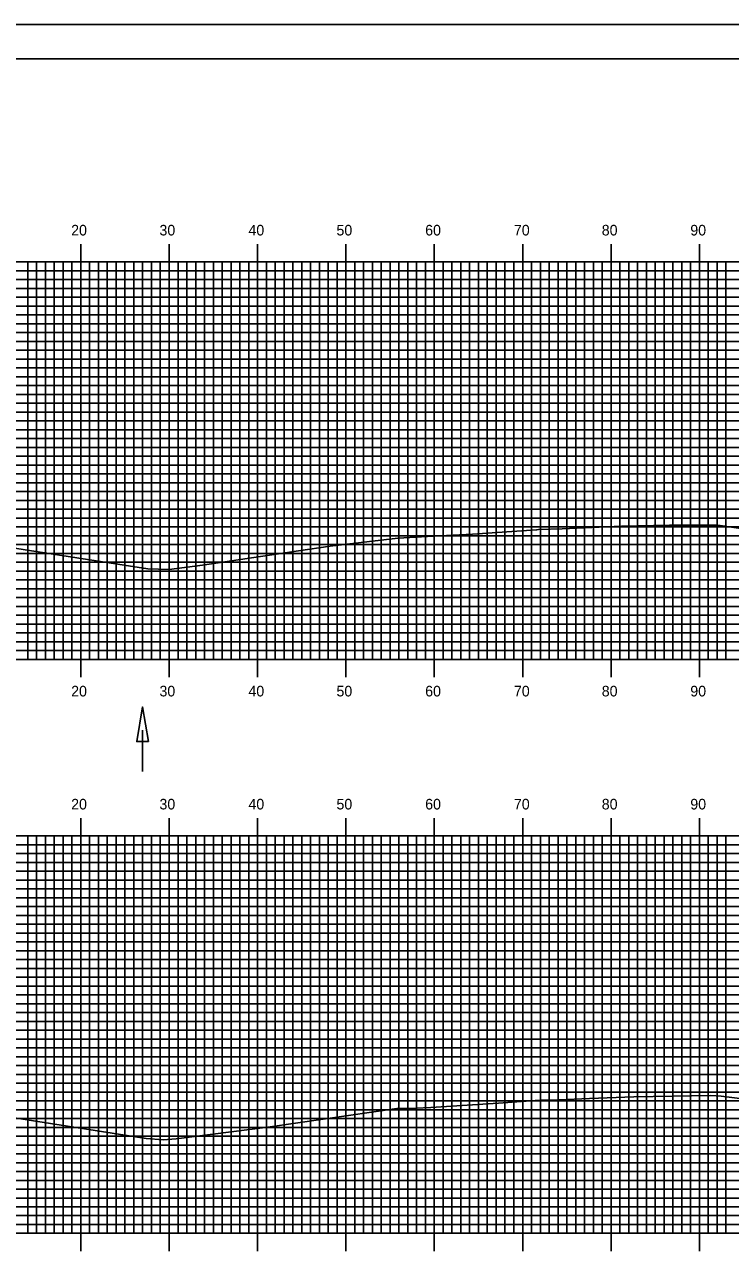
# Model space of a CAD drawing. Extents: x 851533 to 851876, y 366605 to 366825.
# Drawn here: x 851712.1 to 851792, y 366685.6 to 366824.9 of the extents above; entities that cross this region are included whole.
import ezdxf

# ---------------------------------------------------------------- set-up
doc = ezdxf.new("R2010")
doc.units = 0
for name, color, linetype in [('BORDER', 7, 'Continuous'), ('D_Drainage_Ditch_Line', 7, 'Continuous'), ('H_V ANNOTATION', 7, 'Continuous'), ('M_Roadway_Centerline', 7, 'Continuous'), ('MAJOR', 7, 'Continuous'), ('MINOR', 7, 'Continuous'), ('PLOT BOUNDARY', 7, 'Continuous'), ('S_Roadway_Centerline', 7, 'Continuous')]:
    doc.layers.add(name, color=color, linetype=linetype)

msp = doc.modelspace()

# ---------------------------------------------------------------- linework, layer by layer
at = {"layer": 'BORDER'}
msp.add_lwpolyline([(851548.85, 366611.06), (851868.85, 366611.06), (851868.85, 366821.06), (851548.85, 366821.06)], close=True, dxfattribs=at)
at = {"layer": 'D_Drainage_Ditch_Line'}
msp.add_line((851725.44, 366745.05), (851725.44, 366740.35), dxfattribs=at)
msp.add_lwpolyline([(851726.1, 366743.74), (851724.78, 366743.74), (851725.44, 366747.68)], close=True, dxfattribs=at)
at = {"layer": 'MAJOR'}
for p, q in [((851718.45, 366800.06), (851718.45, 366798.06)), ((851728.45, 366800.06), (851728.45, 366798.06)), ((851738.45, 366800.06), (851738.45, 366798.06)), ((851748.45, 366800.06), (851748.45, 366798.06)), ((851758.45, 366800.06), (851758.45, 366798.06)), ((851768.45, 366800.06), (851768.45, 366798.06)), ((851778.45, 366800.06), (851778.45, 366798.06)), ((851788.45, 366800.06), (851788.45, 366798.06)), ((851558.45, 366798.06), (851838.45, 366798.06)), ((851558.45, 366798.06), (851838.45, 366798.06)), ((851718.45, 366753.06), (851718.45, 366798.06)), ((851728.45, 366753.06), (851728.45, 366798.06)), ((851738.45, 366753.06), (851738.45, 366798.06)), ((851748.45, 366753.06), (851748.45, 366798.06)), ((851758.45, 366753.06), (851758.45, 366798.06)), ((851768.45, 366753.06), (851768.45, 366798.06)), ((851778.45, 366753.06), (851778.45, 366798.06)), ((851788.45, 366753.06), (851788.45, 366798.06)), ((851558.45, 366793.06), (851838.45, 366793.06)), ((851558.45, 366788.06), (851838.45, 366788.06)), ((851558.45, 366783.06), (851838.45, 366783.06)), ((851558.45, 366778.06), (851838.45, 366778.06)), ((851558.45, 366773.06), (851838.45, 366773.06)), ((851558.45, 366768.06), (851838.45, 366768.06)), ((851558.45, 366763.06), (851838.45, 366763.06)), ((851558.45, 366758.06), (851838.45, 366758.06)), ((851558.45, 366753.06), (851838.45, 366753.06)), ((851558.45, 366753.06), (851838.45, 366753.06)), ((851718.45, 366751.05), (851718.45, 366753.06)), ((851728.45, 366751.05), (851728.45, 366753.06)), ((851738.45, 366751.05), (851738.45, 366753.06)), ((851748.45, 366751.05), (851748.45, 366753.06)), ((851758.45, 366751.05), (851758.45, 366753.06)), ((851768.45, 366751.05), (851768.45, 366753.06)), ((851778.45, 366751.05), (851778.45, 366753.06)), ((851788.45, 366751.05), (851788.45, 366753.06)), ((851718.45, 366735.06), (851718.45, 366733.06)), ((851728.45, 366735.06), (851728.45, 366733.06)), ((851738.45, 366735.06), (851738.45, 366733.06)), ((851748.45, 366735.06), (851748.45, 366733.06)), ((851758.45, 366735.06), (851758.45, 366733.06)), ((851768.45, 366735.06), (851768.45, 366733.06)), ((851778.45, 366735.06), (851778.45, 366733.06)), ((851788.45, 366735.06), (851788.45, 366733.06)), ((851558.45, 366733.06), (851838.45, 366733.06)), ((851558.45, 366733.06), (851838.45, 366733.06)), ((851718.45, 366688.06), (851718.45, 366733.06)), ((851728.45, 366688.06), (851728.45, 366733.06)), ((851738.45, 366688.06), (851738.45, 366733.06)), ((851748.45, 366688.06), (851748.45, 366733.06)), ((851758.45, 366688.06), (851758.45, 366733.06)), ((851768.45, 366688.06), (851768.45, 366733.06)), ((851778.45, 366688.06), (851778.45, 366733.06)), ((851788.45, 366688.06), (851788.45, 366733.06)), ((851558.45, 366728.06), (851838.45, 366728.06)), ((851558.45, 366723.06), (851838.45, 366723.06)), ((851558.45, 366718.06), (851838.45, 366718.06)), ((851558.45, 366713.06), (851838.45, 366713.06)), ((851558.45, 366708.06), (851838.45, 366708.06)), ((851558.45, 366703.06), (851838.45, 366703.06)), ((851558.45, 366698.06), (851838.45, 366698.06)), ((851558.45, 366693.06), (851838.45, 366693.06)), ((851558.45, 366688.06), (851838.45, 366688.06)), ((851558.45, 366688.06), (851838.45, 366688.06)), ((851718.45, 366686.05), (851718.45, 366688.06)), ((851728.45, 366686.05), (851728.45, 366688.06)), ((851738.45, 366686.05), (851738.45, 366688.06)), ((851748.45, 366686.05), (851748.45, 366688.06)), ((851758.45, 366686.05), (851758.45, 366688.06)), ((851768.45, 366686.05), (851768.45, 366688.06)), ((851778.45, 366686.05), (851778.45, 366688.06)), ((851788.45, 366686.05), (851788.45, 366688.06))]:
    msp.add_line(p, q, dxfattribs=at)
at = {"layer": 'MINOR'}
for p, q in [((851558.45, 366797.06), (851838.45, 366797.06)), ((851712.45, 366753.06), (851712.45, 366798.06)), ((851713.45, 366753.06), (851713.45, 366798.06)), ((851714.45, 366753.06), (851714.45, 366798.06)), ((851715.45, 366753.06), (851715.45, 366798.06)), ((851716.45, 366753.06), (851716.45, 366798.06)), ((851717.45, 366753.06), (851717.45, 366798.06)), ((851719.45, 366753.06), (851719.45, 366798.06)), ((851720.45, 366753.06), (851720.45, 366798.06)), ((851721.45, 366753.06), (851721.45, 366798.06)), ((851722.45, 366753.06), (851722.45, 366798.06)), ((851723.45, 366753.06), (851723.45, 366798.06)), ((851724.45, 366753.06), (851724.45, 366798.06)), ((851725.45, 366753.06), (851725.45, 366798.06)), ((851726.45, 366753.06), (851726.45, 366798.06)), ((851727.45, 366753.06), (851727.45, 366798.06)), ((851729.45, 366753.06), (851729.45, 366798.06)), ((851730.45, 366753.06), (851730.45, 366798.06)), ((851731.45, 366753.06), (851731.45, 366798.06)), ((851732.45, 366753.06), (851732.45, 366798.06)), ((851733.45, 366753.06), (851733.45, 366798.06)), ((851734.45, 366753.06), (851734.45, 366798.06)), ((851735.45, 366753.06), (851735.45, 366798.06)), ((851736.45, 366753.06), (851736.45, 366798.06)), ((851737.45, 366753.06), (851737.45, 366798.06)), ((851739.45, 366753.06), (851739.45, 366798.06)), ((851740.45, 366753.06), (851740.45, 366798.06)), ((851741.45, 366753.06), (851741.45, 366798.06)), ((851742.45, 366753.06), (851742.45, 366798.06)), ((851743.45, 366753.06), (851743.45, 366798.06)), ((851744.45, 366753.06), (851744.45, 366798.06)), ((851745.45, 366753.06), (851745.45, 366798.06)), ((851746.45, 366753.06), (851746.45, 366798.06)), ((851747.45, 366753.06), (851747.45, 366798.06)), ((851749.45, 366753.06), (851749.45, 366798.06)), ((851750.45, 366753.06), (851750.45, 366798.06)), ((851751.45, 366753.06), (851751.45, 366798.06)), ((851752.45, 366753.06), (851752.45, 366798.06)), ((851753.45, 366753.06), (851753.45, 366798.06)), ((851754.45, 366753.06), (851754.45, 366798.06)), ((851755.45, 366753.06), (851755.45, 366798.06)), ((851756.45, 366753.06), (851756.45, 366798.06)), ((851757.45, 366753.06), (851757.45, 366798.06)), ((851759.45, 366753.06), (851759.45, 366798.06)), ((851760.45, 366753.06), (851760.45, 366798.06)), ((851761.45, 366753.06), (851761.45, 366798.06)), ((851762.45, 366753.06), (851762.45, 366798.06)), ((851763.45, 366753.06), (851763.45, 366798.06)), ((851764.45, 366753.06), (851764.45, 366798.06)), ((851765.45, 366753.06), (851765.45, 366798.06)), ((851766.45, 366753.06), (851766.45, 366798.06)), ((851767.45, 366753.06), (851767.45, 366798.06)), ((851769.45, 366753.06), (851769.45, 366798.06)), ((851770.45, 366753.06), (851770.45, 366798.06)), ((851771.45, 366753.06), (851771.45, 366798.06)), ((851772.45, 366753.06), (851772.45, 366798.06)), ((851773.45, 366753.06), (851773.45, 366798.06)), ((851774.45, 366753.06), (851774.45, 366798.06)), ((851775.45, 366753.06), (851775.45, 366798.06)), ((851776.45, 366753.06), (851776.45, 366798.06)), ((851777.45, 366753.06), (851777.45, 366798.06)), ((851779.45, 366753.06), (851779.45, 366798.06)), ((851780.45, 366753.06), (851780.45, 366798.06)), ((851781.45, 366753.06), (851781.45, 366798.06)), ((851782.45, 366753.06), (851782.45, 366798.06)), ((851783.45, 366753.06), (851783.45, 366798.06)), ((851784.45, 366753.06), (851784.45, 366798.06)), ((851785.45, 366753.06), (851785.45, 366798.06)), ((851786.45, 366753.06), (851786.45, 366798.06)), ((851787.45, 366753.06), (851787.45, 366798.06)), ((851789.45, 366753.06), (851789.45, 366798.06)), ((851790.45, 366753.06), (851790.45, 366798.06)), ((851791.45, 366753.06), (851791.45, 366798.06)), ((851558.45, 366796.06), (851838.45, 366796.06)), ((851558.45, 366795.06), (851838.45, 366795.06)), ((851558.45, 366794.06), (851838.45, 366794.06)), ((851558.45, 366792.06), (851838.45, 366792.06)), ((851558.45, 366791.06), (851838.45, 366791.06)), ((851558.45, 366790.06), (851838.45, 366790.06)), ((851558.45, 366789.06), (851838.45, 366789.06)), ((851558.45, 366787.06), (851838.45, 366787.06)), ((851558.45, 366786.06), (851838.45, 366786.06)), ((851558.45, 366785.06), (851838.45, 366785.06)), ((851558.45, 366784.06), (851838.45, 366784.06)), ((851558.45, 366782.06), (851838.45, 366782.06)), ((851558.45, 366781.06), (851838.45, 366781.06)), ((851558.45, 366780.06), (851838.45, 366780.06)), ((851558.45, 366779.06), (851838.45, 366779.06)), ((851558.45, 366777.06), (851838.45, 366777.06)), ((851558.45, 366776.06), (851838.45, 366776.06)), ((851558.45, 366775.06), (851838.45, 366775.06)), ((851558.45, 366774.06), (851838.45, 366774.06)), ((851558.45, 366772.06), (851838.45, 366772.06)), ((851558.45, 366771.06), (851838.45, 366771.06)), ((851558.45, 366770.06), (851838.45, 366770.06)), ((851558.45, 366769.06), (851838.45, 366769.06)), ((851558.45, 366767.06), (851838.45, 366767.06)), ((851558.45, 366766.06), (851838.45, 366766.06)), ((851558.45, 366765.06), (851838.45, 366765.06)), ((851558.45, 366764.06), (851838.45, 366764.06)), ((851558.45, 366762.06), (851838.45, 366762.06)), ((851558.45, 366761.06), (851838.45, 366761.06)), ((851558.45, 366760.06), (851838.45, 366760.06)), ((851558.45, 366759.06), (851838.45, 366759.06)), ((851558.45, 366757.06), (851838.45, 366757.06)), ((851558.45, 366756.06), (851838.45, 366756.06)), ((851558.45, 366755.06), (851838.45, 366755.06)), ((851558.45, 366754.06), (851838.45, 366754.06)), ((851712.45, 366688.06), (851712.45, 366733.06)), ((851713.45, 366688.06), (851713.45, 366733.06)), ((851714.45, 366688.06), (851714.45, 366733.06)), ((851715.45, 366688.06), (851715.45, 366733.06)), ((851716.45, 366688.06), (851716.45, 366733.06)), ((851717.45, 366688.06), (851717.45, 366733.06)), ((851719.45, 366688.06), (851719.45, 366733.06)), ((851720.45, 366688.06), (851720.45, 366733.06)), ((851721.45, 366688.06), (851721.45, 366733.06)), ((851722.45, 366688.06), (851722.45, 366733.06)), ((851723.45, 366688.06), (851723.45, 366733.06)), ((851724.45, 366688.06), (851724.45, 366733.06)), ((851725.45, 366688.06), (851725.45, 366733.06)), ((851726.45, 366688.06), (851726.45, 366733.06)), ((851727.45, 366688.06), (851727.45, 366733.06)), ((851729.45, 366688.06), (851729.45, 366733.06)), ((851730.45, 366688.06), (851730.45, 366733.06)), ((851731.45, 366688.06), (851731.45, 366733.06)), ((851732.45, 366688.06), (851732.45, 366733.06)), ((851733.45, 366688.06), (851733.45, 366733.06)), ((851734.45, 366688.06), (851734.45, 366733.06)), ((851735.45, 366688.06), (851735.45, 366733.06)), ((851736.45, 366688.06), (851736.45, 366733.06)), ((851737.45, 366688.06), (851737.45, 366733.06)), ((851739.45, 366688.06), (851739.45, 366733.06)), ((851740.45, 366688.06), (851740.45, 366733.06)), ((851741.45, 366688.06), (851741.45, 366733.06)), ((851742.45, 366688.06), (851742.45, 366733.06)), ((851743.45, 366688.06), (851743.45, 366733.06)), ((851744.45, 366688.06), (851744.45, 366733.06)), ((851745.45, 366688.06), (851745.45, 366733.06)), ((851746.45, 366688.06), (851746.45, 366733.06)), ((851747.45, 366688.06), (851747.45, 366733.06)), ((851749.45, 366688.06), (851749.45, 366733.06)), ((851750.45, 366688.06), (851750.45, 366733.06)), ((851751.45, 366688.06), (851751.45, 366733.06)), ((851752.45, 366688.06), (851752.45, 366733.06)), ((851753.45, 366688.06), (851753.45, 366733.06)), ((851754.45, 366688.06), (851754.45, 366733.06)), ((851755.45, 366688.06), (851755.45, 366733.06)), ((851756.45, 366688.06), (851756.45, 366733.06)), ((851757.45, 366688.06), (851757.45, 366733.06)), ((851759.45, 366688.06), (851759.45, 366733.06)), ((851760.45, 366688.06), (851760.45, 366733.06)), ((851761.45, 366688.06), (851761.45, 366733.06)), ((851762.45, 366688.06), (851762.45, 366733.06)), ((851763.45, 366688.06), (851763.45, 366733.06)), ((851764.45, 366688.06), (851764.45, 366733.06)), ((851765.45, 366688.06), (851765.45, 366733.06)), ((851766.45, 366688.06), (851766.45, 366733.06)), ((851767.45, 366688.06), (851767.45, 366733.06)), ((851769.45, 366688.06), (851769.45, 366733.06)), ((851770.45, 366688.06), (851770.45, 366733.06)), ((851771.45, 366688.06), (851771.45, 366733.06)), ((851772.45, 366688.06), (851772.45, 366733.06)), ((851773.45, 366688.06), (851773.45, 366733.06)), ((851774.45, 366688.06), (851774.45, 366733.06)), ((851775.45, 366688.06), (851775.45, 366733.06)), ((851776.45, 366688.06), (851776.45, 366733.06)), ((851777.45, 366688.06), (851777.45, 366733.06)), ((851779.45, 366688.06), (851779.45, 366733.06)), ((851780.45, 366688.06), (851780.45, 366733.06)), ((851781.45, 366688.06), (851781.45, 366733.06)), ((851782.45, 366688.06), (851782.45, 366733.06)), ((851783.45, 366688.06), (851783.45, 366733.06)), ((851784.45, 366688.06), (851784.45, 366733.06)), ((851785.45, 366688.06), (851785.45, 366733.06)), ((851786.45, 366688.06), (851786.45, 366733.06)), ((851787.45, 366688.06), (851787.45, 366733.06)), ((851789.45, 366688.06), (851789.45, 366733.06)), ((851790.45, 366688.06), (851790.45, 366733.06)), ((851791.45, 366688.06), (851791.45, 366733.06)), ((851558.45, 366732.06), (851838.45, 366732.06)), ((851558.45, 366731.06), (851838.45, 366731.06)), ((851558.45, 366730.06), (851838.45, 366730.06)), ((851558.45, 366729.06), (851838.45, 366729.06)), ((851558.45, 366727.06), (851838.45, 366727.06)), ((851558.45, 366726.06), (851838.45, 366726.06)), ((851558.45, 366725.06), (851838.45, 366725.06)), ((851558.45, 366724.06), (851838.45, 366724.06)), ((851558.45, 366722.06), (851838.45, 366722.06)), ((851558.45, 366721.06), (851838.45, 366721.06)), ((851558.45, 366720.06), (851838.45, 366720.06)), ((851558.45, 366719.06), (851838.45, 366719.06)), ((851558.45, 366717.06), (851838.45, 366717.06)), ((851558.45, 366716.06), (851838.45, 366716.06)), ((851558.45, 366715.06), (851838.45, 366715.06)), ((851558.45, 366714.06), (851838.45, 366714.06)), ((851558.45, 366712.06), (851838.45, 366712.06)), ((851558.45, 366711.06), (851838.45, 366711.06)), ((851558.45, 366710.06), (851838.45, 366710.06)), ((851558.45, 366709.06), (851838.45, 366709.06)), ((851558.45, 366707.06), (851838.45, 366707.06)), ((851558.45, 366706.06), (851838.45, 366706.06)), ((851558.45, 366705.06), (851838.45, 366705.06)), ((851558.45, 366704.06), (851838.45, 366704.06)), ((851558.45, 366702.06), (851838.45, 366702.06)), ((851558.45, 366701.06), (851838.45, 366701.06)), ((851558.45, 366700.06), (851838.45, 366700.06)), ((851558.45, 366699.06), (851838.45, 366699.06)), ((851558.45, 366697.06), (851838.45, 366697.06)), ((851558.45, 366696.06), (851838.45, 366696.06)), ((851558.45, 366695.06), (851838.45, 366695.06)), ((851558.45, 366694.06), (851838.45, 366694.06)), ((851558.45, 366692.06), (851838.45, 366692.06)), ((851558.45, 366691.06), (851838.45, 366691.06)), ((851558.45, 366690.06), (851838.45, 366690.06)), ((851558.45, 366689.06), (851838.45, 366689.06))]:
    msp.add_line(p, q, dxfattribs=at)
at = {"layer": 'PLOT BOUNDARY'}
msp.add_lwpolyline([(851532.66, 366604.94), (851872.66, 366604.94), (851872.66, 366824.94), (851532.66, 366824.94)], close=True, dxfattribs=at)
at = {"layer": 'S_Roadway_Centerline'}
for points in [[(851708.81, 366766), (851712.64, 366765.37), (851726.05, 366763.3), (851728.46, 366763.24), (851732.24, 366763.71), (851743.09, 366765.36), (851746.66, 366765.89), (851754.33, 366766.79), (851758.36, 366767), (851762.77, 366767.25), (851770.02, 366767.71), (851770.24, 366767.75), (851772.92, 366767.82), (851779.64, 366768.13), (851785.08, 366768.26), (851790.53, 366768.26), (851797.51, 366767.23)], [(851707.28, 366701.69), (851725.86, 366698.78), (851727.77, 366698.65), (851729.24, 366698.77), (851739.61, 366700.07), (851745.87, 366701), (851754.21, 366702.19), (851756.36, 366702.23), (851758.05, 366702.31), (851765.73, 366702.8), (851770.39, 366703.13), (851771.62, 366703.14), (851776.03, 366703.32), (851781.03, 366703.52), (851789.75, 366703.65), (851790.9, 366703.61), (851794.55, 366703.13)]]:
    msp.add_lwpolyline(points, dxfattribs=at)

# ---------------------------------------------------------------- texts
at = {"layer": 'H_V ANNOTATION'}
for s, p in [('20', (851717.36, 366801.06)), ('30', (851727.35, 366801.06)), ('40', (851737.42, 366801.06)), ('50', (851747.38, 366801.06)), ('60', (851757.42, 366801.06)), ('70', (851767.46, 366801.06)), ('80', (851777.4, 366801.06)), ('90', (851787.42, 366801.06)), ('20', (851717.36, 366748.86)), ('30', (851727.35, 366748.86)), ('40', (851737.42, 366748.86)), ('50', (851747.38, 366748.86)), ('60', (851757.42, 366748.86)), ('70', (851767.46, 366748.86)), ('80', (851777.4, 366748.86)), ('90', (851787.42, 366748.86)), ('20', (851717.36, 366736.06)), ('30', (851727.35, 366736.06)), ('40', (851737.42, 366736.06)), ('50', (851747.38, 366736.06)), ('60', (851757.42, 366736.06)), ('70', (851767.46, 366736.06)), ('80', (851777.4, 366736.06)), ('90', (851787.42, 366736.06))]:
    msp.add_text(s, height=1.2, dxfattribs=at).set_placement(p)
at = {"layer": 'M_Roadway_Centerline'}
for s, p in [('C', (851770.23, 366767.75)), ('L', (851770.24, 366767.74)), ('C', (851770.39, 366703.13)), ('L', (851770.39, 366703.12))]:
    msp.add_text(s, height=0.0146, dxfattribs=at).set_placement(p)

doc.saveas('drawing.dxf')
